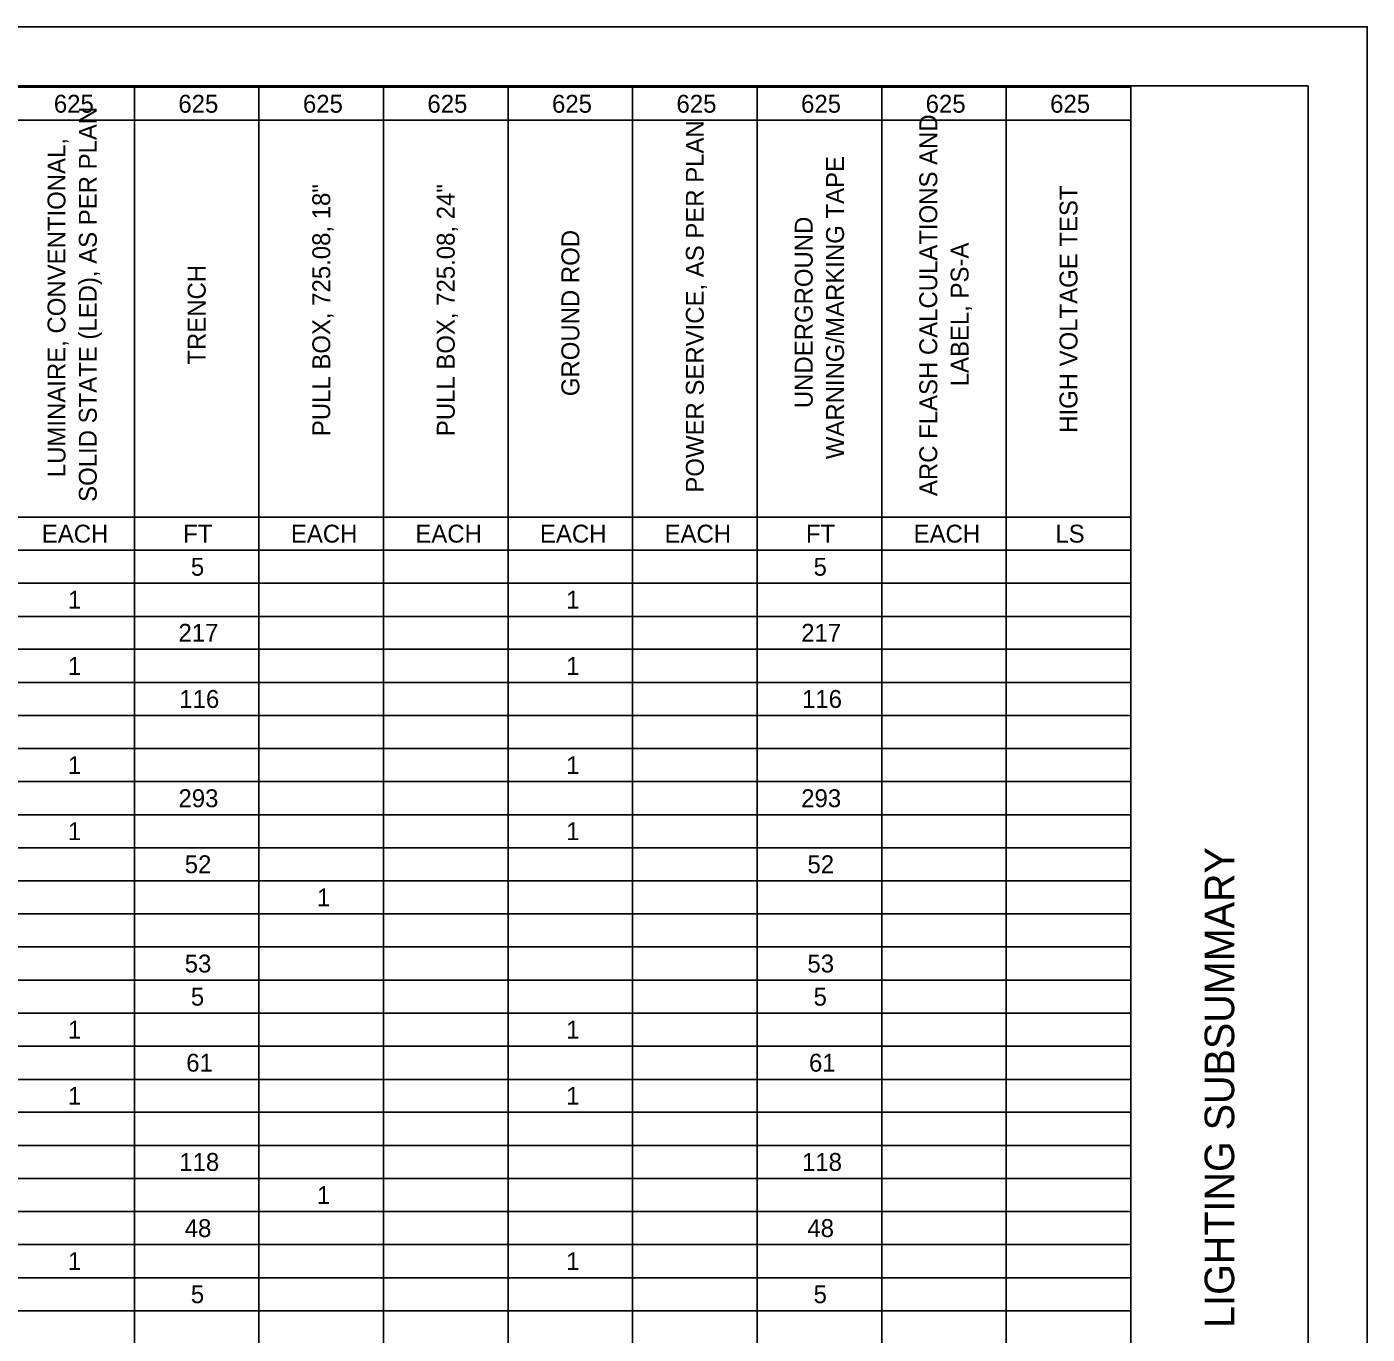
# Model space of a CAD drawing. Extents: x 0 to 34, y 0 to 22.
# Drawn here: x 22.66 to 34, y 10.94 to 22 of the extents above; entities that cross this region are included whole.
import ezdxf

# ---------------------------------------------------------------- set-up
doc = ezdxf.new("R2010")
doc.units = 0
for name, color, linetype in [('Default', 7, 'Continuous'), ('SH_Border', 7, 'Continuous'), ('SH_Cut_Line', 7, 'Continuous'), ('SH_Data', 7, 'Continuous')]:
    doc.layers.add(name, color=color, linetype=linetype)

msp = doc.modelspace()

# ---------------------------------------------------------------- linework, layer by layer
at = {"layer": 'Default'}
for p, q in [((1.496, 21.489), (32, 21.489)), ((23.571, 21.489), (23.571, 0.5)), ((24.625, 21.489), (24.625, 0.5)), ((25.679, 21.489), (25.679, 0.5)), ((26.732, 21.489), (26.732, 0.5)), ((27.786, 21.489), (27.786, 0.5)), ((28.839, 21.489), (28.839, 0.5)), ((29.893, 21.489), (29.893, 0.5)), ((30.946, 21.489), (30.946, 0.5)), ((32, 21.489), (32, 0.5)), ((11.982, 21.209), (32, 21.209)), ((11.982, 17.851), (32, 17.851)), ((1.496, 17.571), (32, 17.571)), ((1.496, 17.291), (32, 17.291)), ((1.496, 17.011), (32, 17.011)), ((1.496, 16.732), (32, 16.732)), ((1.496, 16.452), (32, 16.452)), ((1.496, 16.172), (32, 16.172)), ((1.496, 15.892), (32, 15.892)), ((1.496, 15.612), (32, 15.612)), ((1.496, 15.332), (32, 15.332)), ((1.496, 15.052), (32, 15.052)), ((1.496, 14.773), (32, 14.773)), ((1.496, 14.493), (32, 14.493)), ((1.496, 14.213), (32, 14.213)), ((1.496, 13.933), (32, 13.933)), ((1.496, 13.653), (32, 13.653)), ((1.496, 13.373), (32, 13.373)), ((1.496, 13.093), (32, 13.093)), ((1.496, 12.814), (32, 12.814)), ((1.496, 12.534), (32, 12.534)), ((1.496, 12.254), (32, 12.254)), ((1.496, 11.974), (32, 11.974)), ((1.496, 11.694), (32, 11.694)), ((1.496, 11.414), (32, 11.414)), ((1.496, 11.134), (32, 11.134))]:
    msp.add_line(p, q, dxfattribs=at)
at = {"layer": 'SH_Border'}
msp.add_line((32, 0.5), (32, 21.5), dxfattribs=at)
msp.add_lwpolyline([(1.5, 21.5), (33.5, 21.5), (33.5, 0.5), (1.5, 0.5)], close=True, dxfattribs=at)
at = {"layer": 'SH_Cut_Line'}
msp.add_lwpolyline([(0, 0), (34, 0), (34, 22), (0, 22)], close=True, dxfattribs=at)

# ---------------------------------------------------------------- texts
at = {"layer": 'Default'}
for s, height, p in [('625', 0.1515, (22.89, 21.273)), ('625', 0.1515, (23.943, 21.273)), ('625', 0.1515, (24.997, 21.273)), ('625', 0.1515, (26.05, 21.273)), ('625', 0.1515, (27.104, 21.273)), ('625', 0.1515, (28.157, 21.273)), ('625', 0.1515, (29.211, 21.273)), ('625', 0.1515, (30.265, 21.273)), ('625', 0.1515, (31.318, 21.273)), ('EACH', 0.1515, (22.788, 17.635)), ('FT', 0.1515, (23.984, 17.635)), ('EACH', 0.1515, (24.895, 17.635)), ('EACH', 0.1515, (25.948, 17.635)), ('EACH', 0.1515, (27.002, 17.635)), ('EACH', 0.1515, (28.056, 17.635)), ('FT', 0.1515, (29.252, 17.635)), ('EACH', 0.1515, (30.163, 17.635)), ('LS', 0.1515, (31.362, 17.635)), ('5', 0.151, (24.049, 17.355)), ('5', 0.151, (29.317, 17.355)), ('1', 0.151, (23.009, 17.076)), ('1', 0.151, (27.224, 17.076)), ('217', 0.1515, (23.944, 16.796)), ('217', 0.1515, (29.212, 16.796)), ('1', 0.151, (23.009, 16.516)), ('1', 0.151, (27.224, 16.516)), ('116', 0.1515, (23.951, 16.236)), ('116', 0.1515, (29.219, 16.236)), ('1', 0.151, (23.009, 15.676)), ('1', 0.151, (27.224, 15.676)), ('293', 0.1515, (23.944, 15.396)), ('293', 0.1515, (29.212, 15.396)), ('1', 0.151, (23.009, 15.117)), ('1', 0.151, (27.224, 15.117)), ('52', 0.1515, (23.997, 14.837)), ('52', 0.1515, (29.265, 14.837)), ('1', 0.151, (25.116, 14.557)), ('53', 0.1515, (23.997, 13.997)), ('53', 0.1515, (29.265, 13.997)), ('5', 0.151, (24.049, 13.717)), ('5', 0.151, (29.317, 13.717)), ('1', 0.151, (23.009, 13.438)), ('1', 0.151, (27.224, 13.438)), ('61', 0.1515, (24.01, 13.158)), ('61', 0.1515, (29.278, 13.158)), ('1', 0.151, (23.009, 12.878)), ('1', 0.151, (27.224, 12.878)), ('118', 0.1515, (23.951, 12.318)), ('118', 0.1515, (29.219, 12.318)), ('1', 0.151, (25.116, 12.038)), ('48', 0.1515, (23.997, 11.758)), ('48', 0.1515, (29.264, 11.758)), ('1', 0.151, (23.009, 11.479)), ('1', 0.151, (27.224, 11.479)), ('5', 0.151, (24.049, 11.199)), ('5', 0.151, (29.317, 11.199))]:
    msp.add_text(s, height=height, dxfattribs=at).set_placement(p)
for s, height, p in [('SOLID STATE (LED), AS PER PLAN', 0.15145, (23.253, 17.98)), ('ARC FLASH CALCULATIONS AND ', 0.15145, (30.363, 18.029)), ('POWER SERVICE, AS PER PLAN', 0.15145, (28.388, 18.058)), ('LUMINAIRE, CONVENTIONAL, ', 0.15145, (22.988, 18.189)), ('WARNING/MARKING TAPE', 0.15145, (29.574, 18.341)), ('PULL BOX, 725.08, 18"', 0.15145, (25.228, 18.536)), ('PULL BOX, 725.08, 24"', 0.15145, (26.281, 18.536)), ('HIGH VOLTAGE TEST', 0.15145, (31.549, 18.564)), ('UNDERGROUND ', 0.15145, (29.309, 18.773)), ('GROUND ROD', 0.1515, (27.335, 18.874)), ('LABEL, PS-A', 0.15145, (30.628, 18.958)), ('TRENCH', 0.1515, (24.174, 19.141))]:
    msp.add_text(s, height=height, rotation=90, dxfattribs=at).set_placement(p)
at = {"layer": 'SH_Data'}
msp.add_text('LIGHTING SUBSUMMARY', height=0.25, rotation=90, dxfattribs=at).set_placement((32.875, 10.99))

doc.saveas('drawing.dxf')
